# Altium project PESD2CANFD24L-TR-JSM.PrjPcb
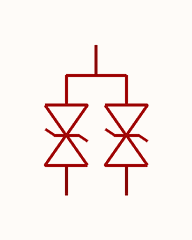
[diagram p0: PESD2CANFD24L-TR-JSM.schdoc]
1 sheet, 1 parts. Net scope: global (net labels, ports and power ports of the same name join across sheets).

## Sheet PESD2CANFD24L-TR-JSM.schdoc
size 127 x 101 mm

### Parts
D?  pesd2canfd24l-tr-jsm  [SOT-23-3_L2.9-W1.3-P1.90-LS2.4-BR]  (value not drawn)

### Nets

Not connected (* = marked no-connect by the designer): D? 1 2 3

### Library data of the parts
D? = pesd2canfd24l-tr-jsm: 极性:双向;反向截止电压(Vrwm):24V;钳位电压:60V;峰值脉冲电流(Ipp):4A@8/20us;峰值脉冲功率(Ppp):230W@8/20us;击穿电压(VBR):30.5V;; Manufacturer: JSMSEMI(杰盛微); AddInBom: yes; ModelId: c62791f0466c4ae2a892c056b845b0ca; ModelName: SOT-23-3P_L2.9-W1.3-H1.0-LS2.4-P0.95; ModelTransform: 98.425,114.173,0,180,0,0,0.0005,-0.0005,0; Polarity: 双向; Reverse Stand-Off Voltage (Vrwm): 24V; Clamping Voltage: 60V; Voltage - Breakdown: 30.5V; Reverse Leakage Current (Ir): 100nA; Number of Channels: 双路; level of protection: IEC 61000-4-2; Type: ESD; Junction Capacitance: 11pF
